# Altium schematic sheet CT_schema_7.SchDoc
size 405 x 220 mm
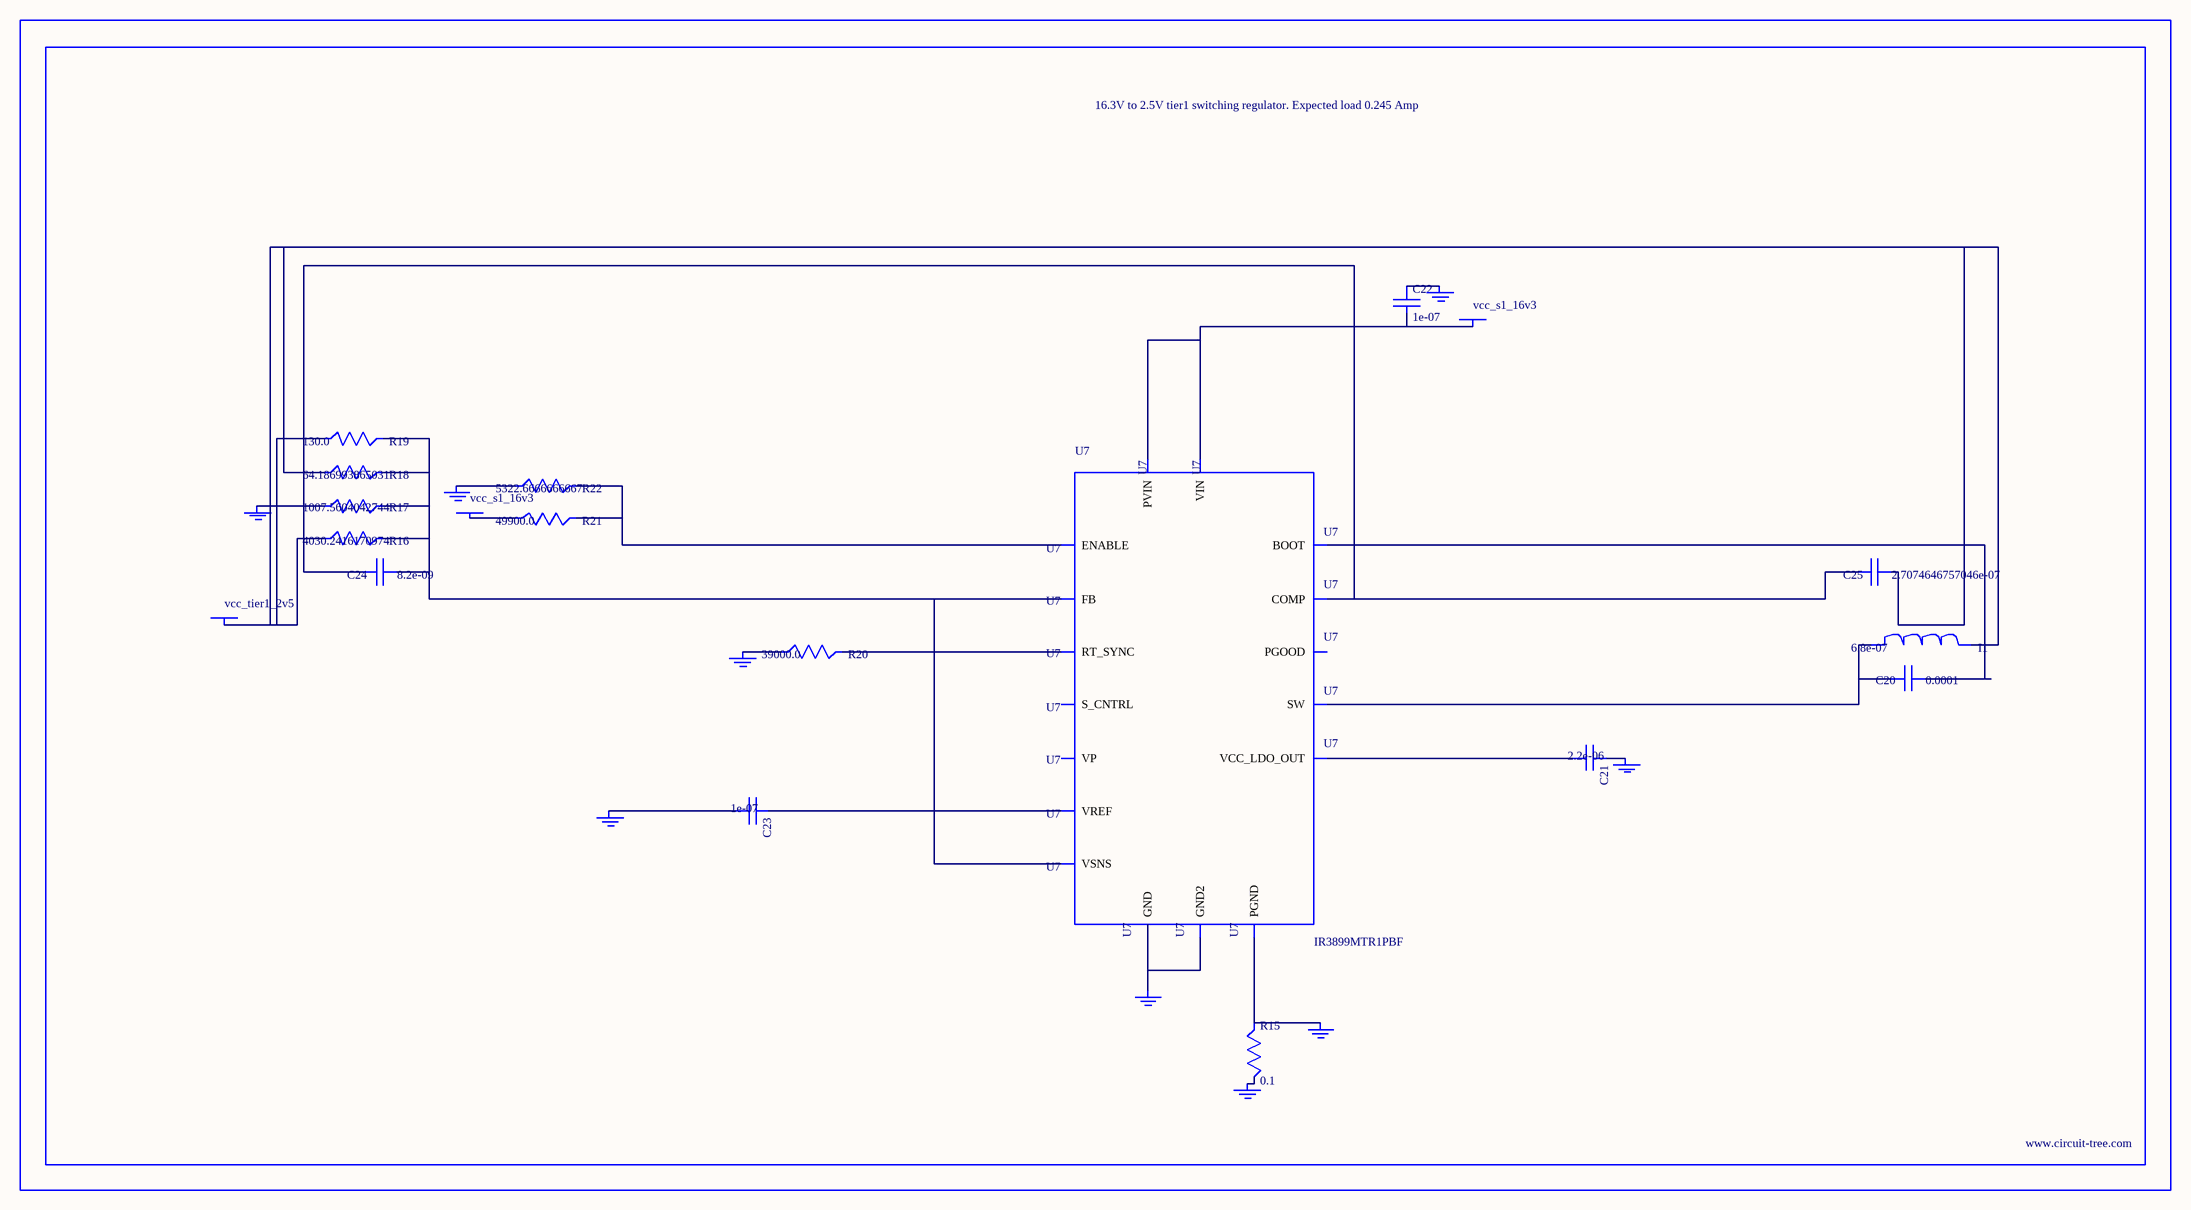
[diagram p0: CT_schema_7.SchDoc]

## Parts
BORDER6  (no value)
C20  0.0001  [C1210]
C21  2.2e-06  [C0603]
C22  1e-07  [C0402]
C23  1e-07  [C0402]
C24  8.2e-09  [C0402]
C25  2.7074646757046e-07  [R0603]
GND_INSTANCE_6_0  (no value)
GND_INSTANCE_6_1  (no value)
GND_INSTANCE_6_2  (no value)
GND_INSTANCE_6_3  (no value)
GND_INSTANCE_6_4  (no value)
GND_INSTANCE_6_5  (no value)
GND_INSTANCE_6_6  (no value)
GND_INSTANCE_6_7  (no value)
GND_INSTANCE_6_8  (no value)
I1  6.8e-07  [IND25X25CZ]
POWER_INSTANCE_6_0  vcc_s1_16v3
POWER_INSTANCE_6_1  vcc_s1_16v3
POWER_INSTANCE_6_2  vcc_tier1_2v5
R15  0.1  [R0603]
R16  4030.2416170974  [R0603]
R17  1007.5604042744  [R0603]
R18  64.186993865031  [R0603]
R19  130.0  [R0603]
R20  39000.0  [R0603]
R21  49900.0  [R0603]
R22  5322.6666666667  [R0603]
U7  IR3899MTR1PBF  [IR3899MTR1PBF]

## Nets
NetC20_1: C20.1 U7.14(BOOT)
NetC20_2: C20.2 I1.1 U7.12(SW)
NetC21_1: C21.1 GND_INSTANCE_6_4.0(GND)
NetC21_2: C21.2 U7.10(VCC_LDO_OUT)
NetC22_1: C22.1 GND_INSTANCE_6_3.0(GND)
NetC22_2: C22.2 POWER_INSTANCE_6_0.0(PWR) U7.9(VIN) U7.13(PVIN)
NetC23_1: C23.1 U7.2(VREF)
NetC23_2: C23.2 GND_INSTANCE_6_1.0(GND)
NetC24_1: C24.1 R16.2 R17.2 R18.2 R19.2 U7.1(FB) U7.8(VSNS)
NetC24_2: C24.2 C25.2 U7.3(COMP)
NetC25_1: C25.1 I1.2 POWER_INSTANCE_6_2.0(PWR) R16.1 R18.1 R19.1
NetGND_INSTANCE_6_0_0: GND_INSTANCE_6_0.0(GND) R17.1
NetGND_INSTANCE_6_2_0: GND_INSTANCE_6_2.0(GND) R20.1
NetGND_INSTANCE_6_5_0: GND_INSTANCE_6_5.0(GND) R15.2
NetGND_INSTANCE_6_6_0: GND_INSTANCE_6_6.0(GND) R15.1 U7.11(PGND)
NetGND_INSTANCE_6_7_0: GND_INSTANCE_6_7.0(GND) R22.1
NetGND_INSTANCE_6_8_0: GND_INSTANCE_6_8.0(GND) U7.4(GND) U7.17(GND2)
NetPOWER_INSTANCE_6_1_0: POWER_INSTANCE_6_1.0(PWR) R21.1
NetR20_2: R20.2 U7.5(RT_SYNC)
NetR21_2: R21.2 R22.2 U7.15(ENABLE)

Not connected (* = marked no-connect by the designer): U7 6(S_CNTRL) 7(PGOOD) 16(VP)

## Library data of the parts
BORDER6 = BORDER_PAGE6
C20 = GRM32ER61A107ME20L
C21 = C0603C225K8RACTU
C22 C23 = C0402C104K3RACTU
C24 = C0402C822K3RAC
C25 = C25
GND_INSTANCE_6_0-GND_INSTANCE_6_8 = GND
I1 = IHLP2525CZERR68M01
POWER_INSTANCE_6_0-POWER_INSTANCE_6_2 = PWR
R15 = ERJ-3RSFR10V
R16 = R16
R17 = R17
R18 = R18
R19 = RC0603JR-07130RL
R20 = RC0603JR-0739KL
R21 = RC0603FR-0749K9
R22 = R22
